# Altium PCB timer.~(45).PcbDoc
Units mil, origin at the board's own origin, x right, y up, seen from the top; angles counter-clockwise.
Board outline 1968.5 x 1968.5 mil, 2 copper layers (Top Layer, Bottom Layer); 56 components, 43 nets, 162 pads, 38 vias.
Unrouted connection lines stored in the file: 7.
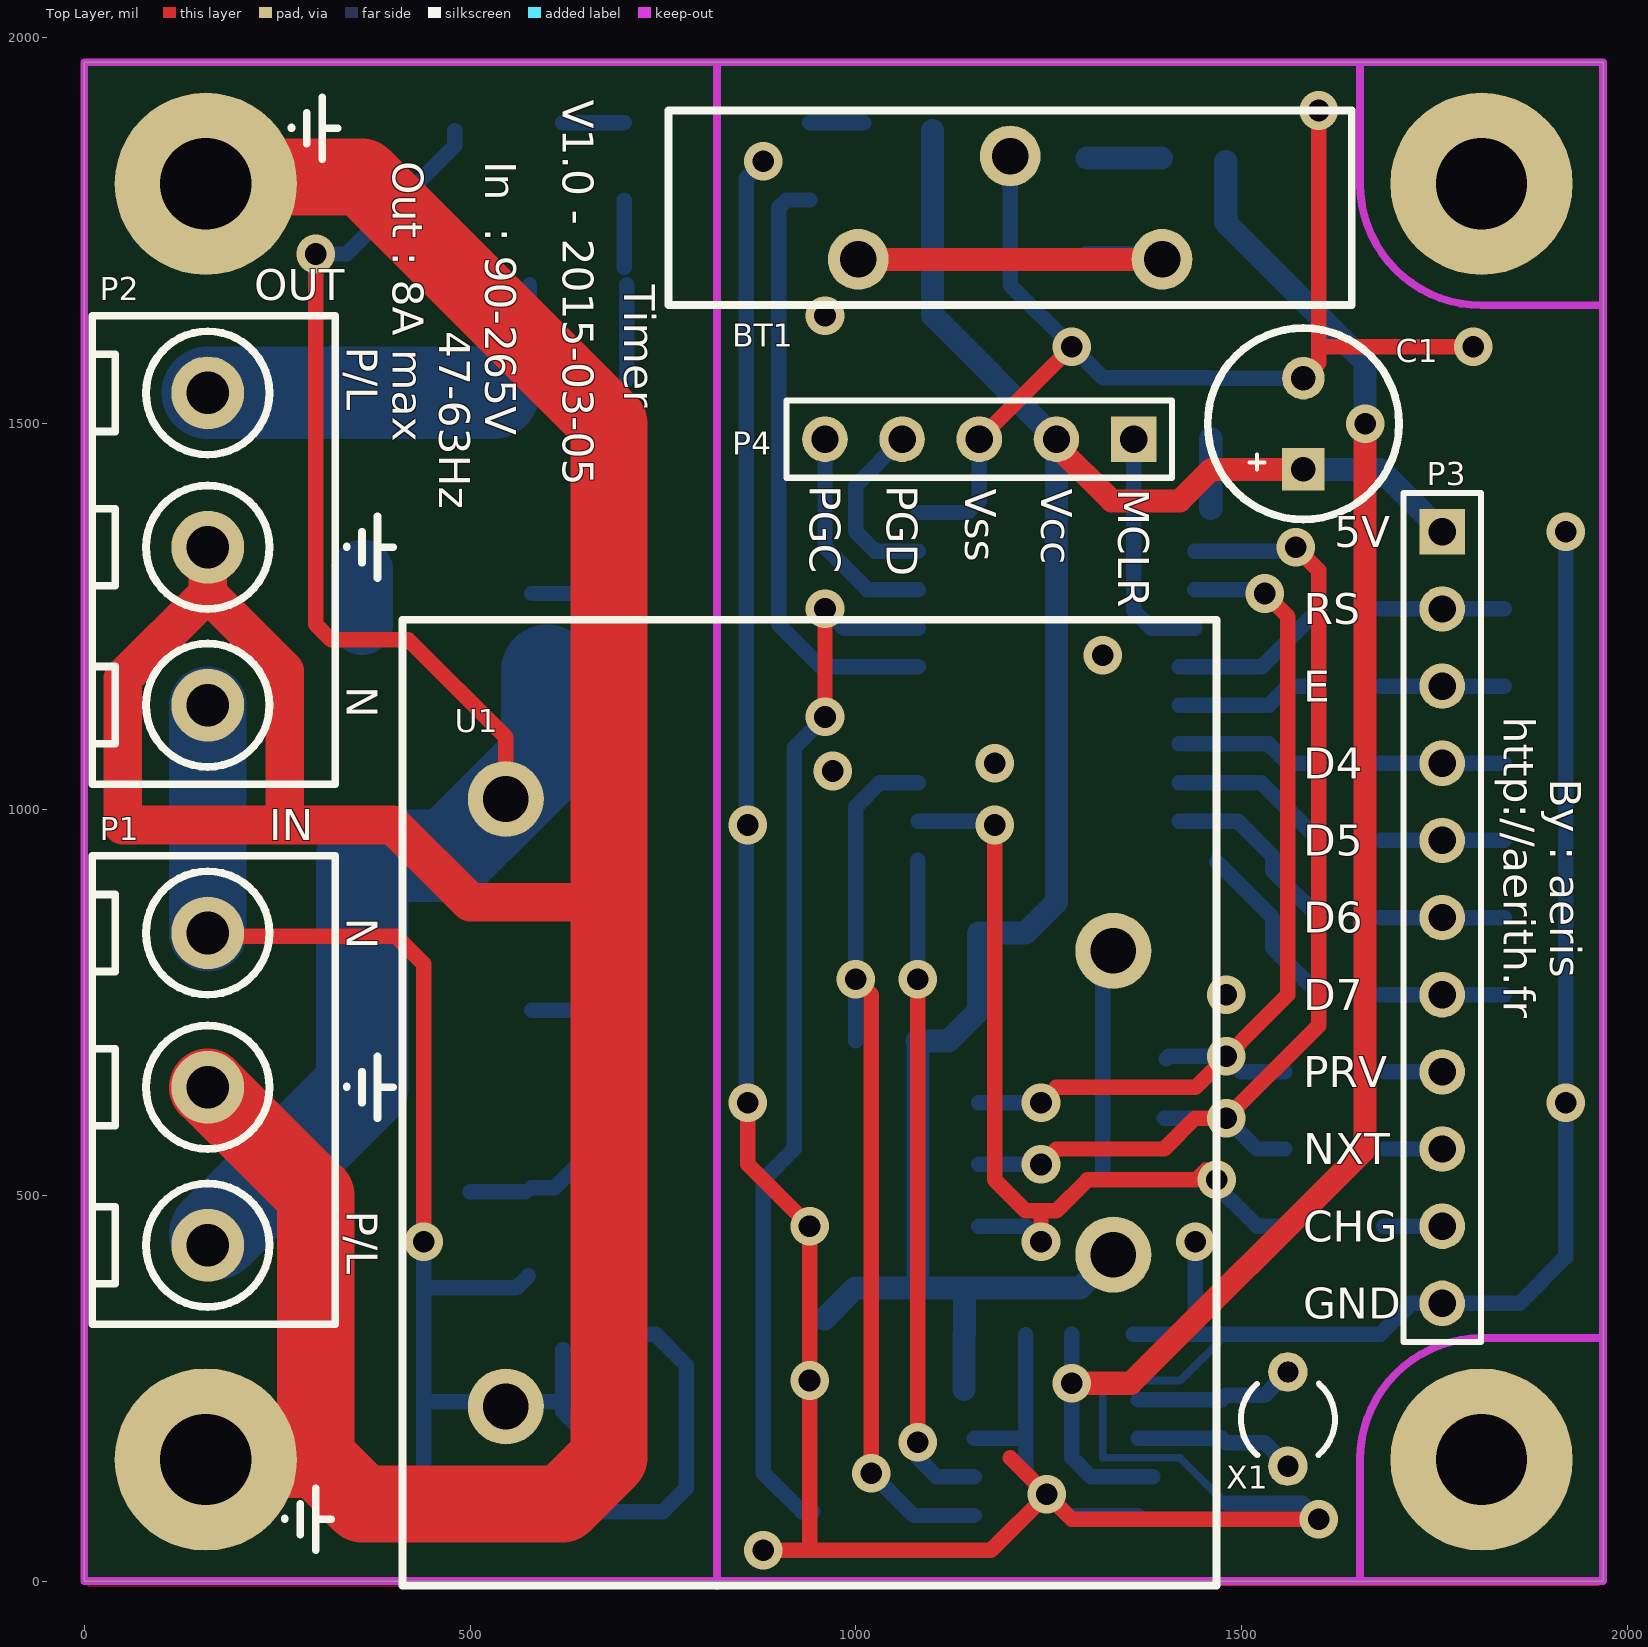
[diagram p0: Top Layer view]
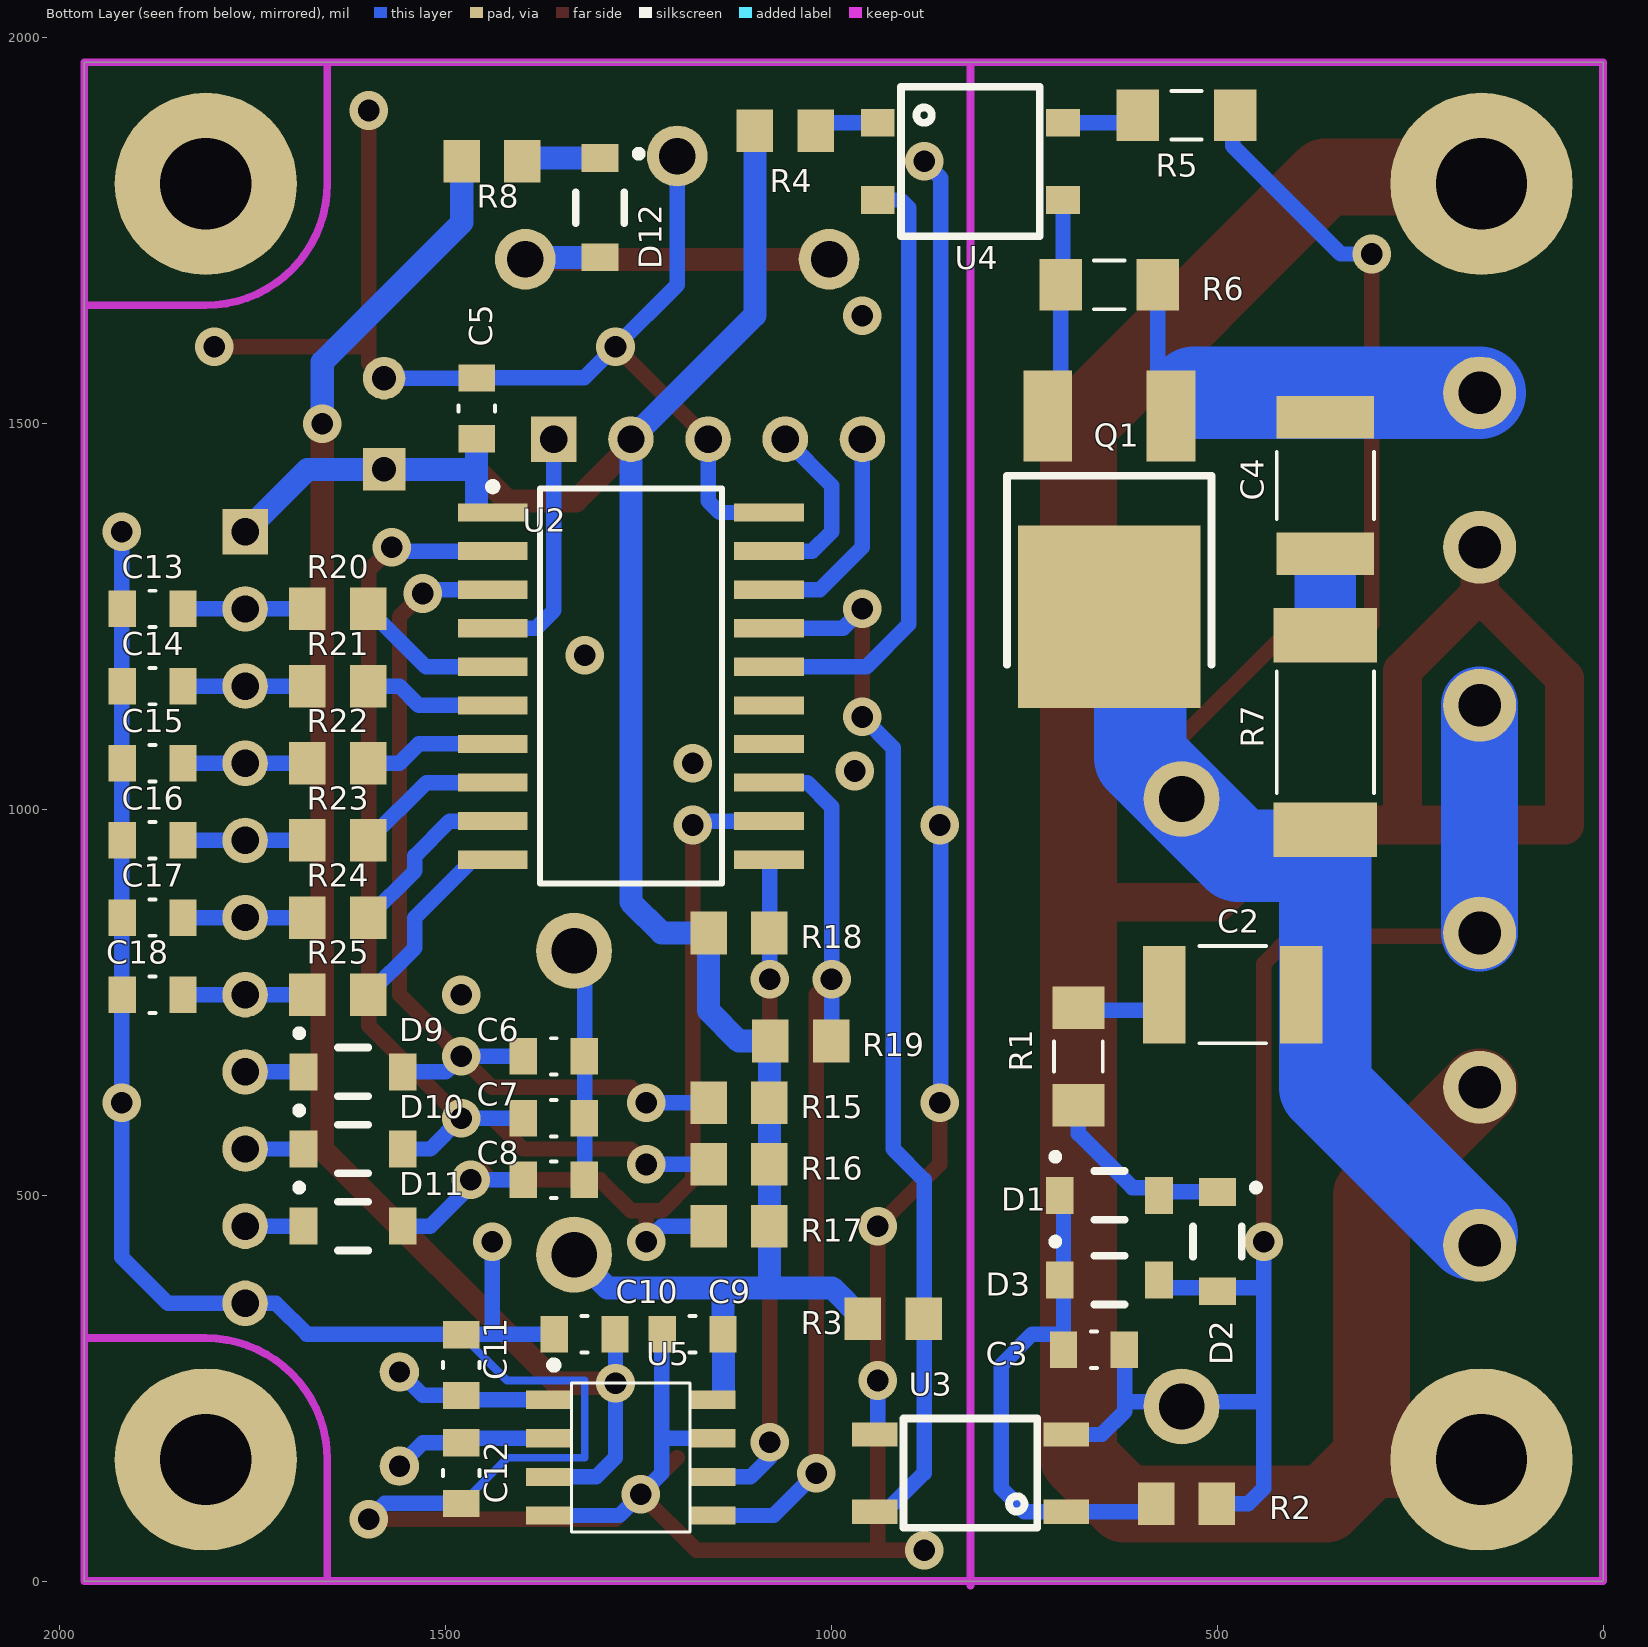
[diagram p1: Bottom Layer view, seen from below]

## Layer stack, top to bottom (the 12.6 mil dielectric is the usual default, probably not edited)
Top Layer: signal copper 1.4
Dielectric: core 12.6, FR-4, Dk 4.8
Bottom Layer: signal copper 1.4

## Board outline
0,0 1968.5,0 1968.5,1968.5 0,1968.5

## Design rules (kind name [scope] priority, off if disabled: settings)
Clearance RTC [InNetClass('RTC')] p1: gap=8
Clearance Earth [InNet('EARTH')] p2: gap=20
Clearance HT [InNetClass('HT') vs InNetClass('HT')] p3: gap=78.74
Clearance "plan masse" [All vs InNet('GND')] p4: gap=10
Clearance [All] p5: gap=20
HoleSize [All] p1: absolutevalues=TRUE maxlimit=196.85 minlimit=23.62 maxpercent=80.000 minpercent=20.000
PlaneConnect PlaneConnect_Via [isVia] p1: planeconnectstyle=Direct reliefexpansion=20 reliefentries=4 reliefconductorwidth=10 reliefairgap=10
PlaneConnect [All] p2: planeconnectstyle=Direct reliefexpansion=20 reliefentries=4 reliefconductorwidth=10 reliefairgap=10
PolygonConnect PolygonConnect_Via [IsVia] p1: connectstyle=Direct reliefconductorwidth=20 reliefentries=4 polygonreliefangle="90 Angle" airgapwidth=10
PolygonConnect [All] p2: connectstyle=Direct reliefconductorwidth=20 reliefentries=4 polygonreliefangle="90 Angle" airgapwidth=10
RoutingVias [All] p1: holewidth=39.37 width=78.74 viastyle="Through Hole" minholewidth=23.62 minwidth=31.5 maxholewidth=39.37 maxwidth=78.74
SilkToSolderMaskClearance SilkscreenOverComponentPads [IsPad] p1: minsilkscreentomaskgap=10 clearancetoexposedcopper=TRUE
SolderMaskExpansion [All] p1: expansion=4
Width overlay_width [(OnLayer('Top Overlay') OR OnLayer('Bottom Overlay'))] p1: maxlimit=10 minlimit=5 preferedwidth=10
Width [All] p2: maxlimit=150 minlimit=10 preferedwidth=20
25 further rules are at their usual default settings.

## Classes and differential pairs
net class RTC: NetC10_1 NetC11_1 NetC12_1
net class HT: N NetC4_1 NetC4_2 P

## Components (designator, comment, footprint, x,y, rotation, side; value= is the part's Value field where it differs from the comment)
BT1 "CR2032" BAT_2032 1200,1780 r0 top locked
C1 "470µ" CAP_6.3x2.5 1580,1500 r90 top locked
C2 "10n 400V" C1812 480,760 r0 bottom
C3 "10n" C0805 660,300 r180 bottom
C4 "10n 400V" C1812 360,1420 r90 bottom
C5 "100n" C0805 1460,1520 r270 bottom
C6 "100n" C0805 1360,680 r180 bottom
C7 "100n" C0805 1360,600 r180 bottom
C8 "100n" C0805 1360,520 r180 bottom
C9 "100n" C0805 1180,320 r0 bottom
C10 "100p" C0805 1320,320 r0 bottom
C11 "15p" C0805 1480,280 r90 bottom
C12 "15p" C0805 1480,140 r270 bottom
C13 "47p" C0805 1880,1260 r0 bottom
C14 "47p" C0805 1880,1160 r0 bottom
C15 "47p" C0805 1880,1060 r0 bottom
C16 "47p" C0805 1880,960 r0 bottom
C17 "47p" C0805 1880,860 r0 bottom
C18 "47p" C0805 1880,760 r0 bottom
D1 "MBR0520LT" SOD-123 640,500 r0 bottom
D2 "MBR0520LT" SOD-123 500,440 r90 bottom
D3 "5V1" SOD-123 640,390 r0 bottom
D9 "MBR0520LT" SOD-123 1620,660 r0 bottom
D10 "MBR0520LT" SOD-123 1620,560 r0 bottom
D11 "MBR0520LT" SOD-123 1620,460 r0 bottom
D12 "MBR0520LT" SOD-123 1300,1780 r90 bottom
P1 "5.08x3" "BORNIER 5.08X3" 160,640 r270 top locked
P2 "5.08x3" "BORNIER 5.08X3" 160,1340 r270 top locked
P3 "2.54x11" HDR1X11 1760,1360 r270 top locked
P4 "2.54x5" HDR1X5 1360,1480 r180 top locked
Q1 "BT137S-600D" DPAK 640,1310 r0 bottom
R1 "10k" R1206 680,680 r90 bottom
R2 "100k" R0805 540,100 r180 bottom
R3 "10k" R0805 920,340 r0 bottom
R4 "1k" R0805 1060,1880 r0 bottom
R5 "56" R1206 540,1900 r0 bottom
R6 "330" R1206 640,1680 r0 bottom
R7 "100 1W" R2512 360,1100 r90 bottom
R8 "1k" R0805 1440,1840 r0 bottom
R15 "10k" R0805 1120,620 r180 bottom
R16 "10k" R0805 1120,540 r180 bottom
R17 "10k" R0805 1120,460 r180 bottom
R18 "2k2" R0805 1120,840 r180 bottom
R19 "2k2" R0805 1040,700 r180 bottom
R20 "1k" R0805 1640,1260 r0 bottom
R21 "1k" R0805 1640,1160 r0 bottom
R22 "1k" R0805 1640,1060 r0 bottom
R23 "1k" R0805 1640,960 r0 bottom
R24 "1k" R0805 1640,860 r0 bottom
R25 "1k" R0805 1640,760 r0 bottom
U1 "AC-DC 5V 600mA" "AC-DC 3W" 940,620 r0 top locked
U2 "PIC16F1825" SOIC-20 1260,1160 r180 bottom locked
U3 "PC357N14J00F" OPTO_PC357N14J00F 820,140 r0 bottom
U4 "VOM160RT" OPTO_VOM160RT 820,1840 r180 bottom
U5 "MCP7940N" SOIC-8 1260,160 r180 bottom locked
X1 "32.768kHz" R38 1560,210 r0 top locked

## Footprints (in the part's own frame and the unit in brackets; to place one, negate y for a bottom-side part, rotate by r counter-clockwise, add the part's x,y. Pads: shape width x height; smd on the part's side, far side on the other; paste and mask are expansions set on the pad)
"AC-DC 3W" [mm]
  round 2.5 hole 1.5: 1(-10,10) 2(-10,-10) 3(10,-5) 4(10,5)
  silkscreen extent -13.4,-15.9 13.4,15.9, body extent -13.4,-15.9 13.4,15.9, height 19.5
BAT_2032 [mm] "Battery holder 2032"
  round 2 hole 1.2: +(-5,-1.7) +(5,-1.7) -(0,1.7)
  silkscreen extent -11.25,-3.2 11.25,3.2, body extent -11.25,-3.2 11.25,3.2, height 25
"BORNIER 5.08X3" [mm] "Bornier 5.08x3"
  round 2.4 hole 1.4: 1(-5.08,0) 2(0,0) 3(5.2,0)
  silkscreen extent -7.62,-3.8 7.8,4.2
C0805 [mm]
  rect 0.9x1.2 smd: 1(-1,0) 2(1,0)
  silkscreen extent -0.1,-0.6 0.1,0.6, body extent -1,-0.6 1,0.6, height 1.2
C1812 [mm]
  rect 1.4x3.2 smd: 1(-2.25,0) 2(2.25,0)
  silkscreen extent -1.1,-1.6 1.1,1.6, body extent -2.25,-1.6 2.25,1.6, height 3.2
CAP_6.3x2.5 [mm] "Capacitor throug hole dia=6.3mm, H=11mm, spacing=2.5mm"
  rect 1.4x1.4 hole 0.8: 1(-1.5,0)
  round 1.4 hole 0.8: 2(1.5,0)
  silkscreen extent -3.15,-3.15 3.15,3.15, body extent -3.12,-3.14 3.15,3.14, height 11
DPAK [mm] "DPAK"
  rect 1.6x3 smd: 1(-2.032,-5.08) 3(2.032,-5.08)
  rect 6x6 smd: 2(0,1.524)
  silkscreen extent -3.36,-3.11 3.36,3.11, body extent -3.36,-3.11 3.36,3.11, height 2.38
HDR1X5 [mm] "Connector; Header; 5 Position"
  rect 1.5x1.5 hole 0.9: 1(0,0)
  round 1.5 hole 0.9: 2(2.54,0) 3(5.08,0) 4(7.62,0) 5(10.16,0)
  silkscreen extent -1.27,-1.27 11.43,1.27
HDR1X11 [mm] "Connector; Header; 11 Position"
  rect 1.5x1.5 hole 0.9: 1(0,0)
  round 1.5 hole 0.9: 2(2.54,0) 3(5.08,0) 4(7.62,0) 5(10.16,0) 6(12.7,0) 7(15.24,0) 8(17.78,0) 9(20.32,0) 10(22.86,0) 11(25.4,0)
  silkscreen extent -1.27,-1.27 26.67,1.27
OPTO_PC357N14J00F [mm] "optocoupleur"
  rect 1.5x0.8 smd: 1(-3.15,1.27) 2(-3.15,-1.27) 3(3.15,-1.27) 4(3.15,1.27)
  silkscreen extent -2.2,-1.8 2.2,1.8, body extent -2.2,-1.8 2.2,1.8, height 2.6
OPTO_VOM160RT [mm] "Opto-triac"
  rect 1.11x0.91 smd: 1(-3.048,1.27) 2(-3.048,-1.27) 3(3.048,-1.27) 4(3.048,1.27)
  silkscreen extent -2.28,-2.46 2.28,2.46, body extent -2.28,-2.46 2.28,2.46, height 1.97
R38 [mm] "Crystal, Thru-Hole; 2 Leads; Body 3.1 x 8.2 mm (Dia.xH)"
  round 1.3 hole 0.7: 1(0,1.55) 2(0,-1.55)
  silkscreen extent -1.55,-1.19 1.55,1.17
R0805 [mm] "0.125W"
  rect 1.2x1.4 smd: 1(-1,0) 2(1,0)
  body extent -1,-0.63 1,0.63, height 1.2
R1206 [mm] "0.25W"
  rect 1.4x1.7 smd: 1(-1.6,0) 2(1.6,0)
  silkscreen extent -0.5,-0.8 0.5,0.8, body extent -1.6,-0.8 1.6,0.8, height 1.6
R2512 [mm] "1W"
  rect 1.8x3.4 smd: 1(-3.2,0) 2(3.2,0)
  silkscreen extent -2,-1.6 2,1.6, body extent -3.2,-1.6 3.2,1.6, height 5
SOD-123 [mm] "Diode"
  rect 0.91x1.22 smd: 1(-1.635,0) 2(1.635,0)
  silkscreen extent -0.5,-1.37 1.88,0.8, body extent -1.35,-0.8 1.35,0.8, height 1.17
SOIC-8 [mm] "8-Pin Plastic Narrow Body Small Outline Integrated Circuit 1.27 mm Pitch, IPC Medium Density"
  rect 1.5x0.6 smd: 1(-2.7,1.905) 2(-2.7,0.635) 3(-2.7,-0.635) 4(-2.7,-1.905) 5(2.7,-1.905) 6(2.7,-0.635) 7(2.7,0.635) 8(2.7,1.905)
  silkscreen extent -2.67,-2.45 1.95,3.17, body extent -1.95,-2.45 1.95,2.45, height 1.76
SOIC-20 [mm] "20-Pin Plastic Wide Body Small Outline Integrated Circuit 1.27 mm Pitch, IPC Medium Density"
  rect 2.3x0.6 smd: 1(-4.55,5.715) 2(-4.55,4.445) 3(-4.55,3.175) 4(-4.55,1.905) 5(-4.55,0.635) 6(-4.55,-0.635) 7(-4.55,-1.905) 8(-4.55,-3.175) 9(-4.55,-4.445) 10(-4.55,-5.715) 11(4.55,-5.715) 12(4.55,-4.445) 13(4.55,-3.175) 14(4.55,-1.905) 15(4.55,-0.635) 16(4.55,0.635) 17(4.55,1.905) 18(4.55,3.175) 19(4.55,4.445) 20(4.55,5.715)
  silkscreen extent -4.67,-6.5 3,6.69, body extent -3.75,-6.4 3.75,6.4, height 2.65

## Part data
BT1: library part Battery, "Multicell Battery"
C1: library part "Cap Pol1", "Polarized Capacitor (Radial)"
C2 C3 C4 C5 C6 C7 C8 C9 C10 C11 C12 C13 C14 C15 C16 C17 C18: library part Cap, "Capacitor"
D1 D2 D9 D10 D11 D12: library part "Diode 1N4001", "1 Amp General Purpose Rectifier"
D3: library part "D Zener", "Zener Diode"
P1 P2: library part "Header 3", "Header, 3-Pin"
P3: library part "Header 11", "Header, 11-Pin"
P4: library part "Header 5", "Header, 5-Pin"
Q1: library part Triac, "Silicon Bidirectional Triode Thyristor"
R1 R2 R3 R4 R5 R6 R7 R8 R15 R16 R17 R18 R19 R20 R21 R22 R23 R24 R25: library part Res2, "Resistor"
U1: library part AC-DC
U2: library part PIC16F1829
U3: library part Optoisolator1, "4-Pin Phototransistor Optocoupler"
U4: library part "Opto TRIAC", "Opto-Triac"
U5: library part "RTC- MCP7940N"
X1: library part XTAL, "Crystal Oscillator"

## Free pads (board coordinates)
  round 236.22 hole 118.11: 0(157.48,157.48) 0(157.48,1811.02) 0(1811.02,157.48) 0(1811.02,1811.02)

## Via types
v1: diameter 50, hole 28, Top Layer to Bottom Layer, 38 vias

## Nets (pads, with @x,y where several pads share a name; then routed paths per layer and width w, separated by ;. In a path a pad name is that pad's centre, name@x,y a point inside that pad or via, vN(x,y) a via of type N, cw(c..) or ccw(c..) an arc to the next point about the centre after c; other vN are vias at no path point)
BP_CHG: C8.1 D11.1 R17.1 U2.12 | length 1201.3
  Top Layer w20: v1(1180,980) 1180,520 1220,480 1240,480 ; v1(1240,440) 1240,480 ; v1@1454.33,515.43 1454.33,533.23 1441.1,520 1300,520 1260,480 1240,480
  Bottom Layer w20: U2.12 1175,985 v1(1180,980) ; R17.1 1220,460 v1(1240,440) ; C8.1@1400,520 1460,520 1520,460 D11.1
  other v1: 1467.56,520
BP_NXT: C7.1 D10.1 R16.1 U2.2 | length 1453.4
  Top Layer w20: v1(1240,540) 1260,560 1399.69,560 1439.69,600 v1(1480,600) 1600,720 1600,1310 v1(1570,1340)
  Bottom Layer w20: R16.1 v1(1240,540) ; C7.1 v1(1480,600) 1520,560 D10.1 ; U2.2 1565,1335 v1(1570,1340)
BP_PRV: C6.1 D9.1 R15.1 U2.3 | length 1246.8
  Top Layer w20: v1(1240,620) 1260,640 1440,640 1560,760 1560,1250 v1(1530,1280)
  Bottom Layer w20: R15.1 v1(1240,620) ; C6.1@1402.38,676.99 1405.39,680 v1(1480,680) 1500,660 D9.1 ; U2.3 1525,1285 v1(1530,1280)
EARTH: P1.2 P2.2 pad.0@157.48,157.48 pad.0@157.48,1811.02 | length 4671.4
  Top Layer w50: P2.2 160,1280 ; 680,880 500,880 400,980 260,980 ; 160,1280 50,1170 50,980 260,980 ; 160,1280 260,1180 260,980
  Top Layer w100: pad.0@157.48,1811.02 166.46,1820 360,1820 680,1500 680,880 680,160 620,100 360,100 302.52,157.48 157.48,157.48 300,157.48 300,500 P1.2
GND: BT1.- C1.2 C5.1 C6.2 C7.2 C8.2 C9.2 C10.2 C11.2 C12.2 C13.2 C14.2 C15.2 C16.2 C17.2 C18.2 P3.11 P4.3 U1.4 U2.20 U3.3 U5.4 U5.7 | length 7217.7
  Top Layer w20: v1(860,620) 860,540 v1(940,460) v1(940,260) 940,40 ; v1(880,40) 940,40 ; P4.3 v1(1280,1600) ; 1200,160 v1(1247.5,112.5) ; C1.2 1600,1579.06 1600,1600 ; v1(1600,80) 1280,80 v1(1247.5,112.5) ; v1(1600,1905.98) 1600,1600 ; v1(1800,1600) 1600,1600 ; 940,40 1175,40 v1(1247.5,112.5)
  Bottom Layer w10: C12.2@1479.37,100.63 1420,160 1320,160 1320,260 1420.63,260 C11.2
  Bottom Layer w20: v1@858.19,620 858.19,1818.19 v1(880,1840) ; U3.3@940,194.02 v1(940,260) ; U2.20 1145,1385 1160,1400 P4.3 ; U5.7 1220,185 ; BT1.- 1200,1680 v1(1280,1600) 1320.63,1559.37 C5.1 ; C9.2@1220,319.37 1220,185 ; C8.2@1320,520.63 U1.4@1320,840 ; C10.2 C11.2@1479.37,320 ; U5.4 1275,85 v1(1247.5,112.5) 1220,140 1220,185 ; 1440,320 v1(1440,440) ; C5.1@1460.32,1559.06 C1.2 ; C12.2 1579.37,100.63 v1(1600,80) ; C11.2@1480.63,320 1680,320 1720,360 1860,360 1920,420 v1(1920,1360)
  other v1: 1920,620 1480,760 860,980 970,1050 1180,1060 1320,1200 960,1640
LCD_D4: R22.1 U2.7 | length 191.9
  Bottom Layer w20: U2.7@1419.13,1085 1535,1085 1560,1060 R22.1
LCD_D5: R23.1 U2.8 | length 212.6
  Bottom Layer w20: U2.8@1419.13,1035 1525,1035 1560,1000 1560.63,1000 R23.1
LCD_D6: R24.1 U2.9 | length 244.6
  Bottom Layer w20: U2.9@1419.13,985 1495,985 1540,940 1540,920.63 R24.1
LCD_D7: R25.1 U2.10 | length 227.6
  Bottom Layer w20: U2.10@1467.56,932.44 1540,860 1540,820.63 R25.1
LCD_E: R21.1 U2.6 | length 191.9
  Bottom Layer w20: U2.6@1419.13,1135 1535,1135 1560,1160 R21.1
LCD_RS: R20.1 U2.5 | length 212.6
  Bottom Layer w20: U2.5@1419.13,1185 1525.63,1185 R20.1
MCLR: P4.1 U2.4 | length 310.6
  Bottom Layer w20: P4.1 1360,1258.11 1383.11,1235 U2.4
N: C3.2 D2.1 D3.1 P1.1 P2.3 R2.2 U1.2 U3.2 | length 1834.8
  Top Layer w20: P1.1@164.25,835.75 404.25,835.75 440,800 v1(440,440)
  Bottom Layer w20: 440,380 560,380 D3.1@575.63,395.63 ; v1(440,440) 440,232.6 ; R2.2 460,100 440,120 440,232.6 ; 620,232.6 540,232.6 440,232.6 ; C3.2 620,300 620,220 650,190 U3.2
  Bottom Layer w50: U1.2@540,232.6 U1.2
  Bottom Layer w100: P1.1 P2.3
NetBT1_1: BT1.+ D12.1 | length 488
  Top Layer w30: BT1.+@1003.15,1713.07 BT1.+@1396.85,1713.07
  Bottom Layer w30: D12.1 BT1.+@1394.29,1715.63
NetC2_2: C2.2 R1.2 | length 100
  Bottom Layer w20: C2.2@580,740 R1.2@680,740
NetC3_1: C3.1 D1.2 D3.2 R2.1 U3.1 | length 639.6
  Bottom Layer w20: R2.1@580,90 U3.1 750,90 780,120 780,280 740,320 699.37,320 D1.2@699.37,490
NetC4_1: C4.1 R7.2 | length 70
  Bottom Layer w80: R7.2@360,1240 C4.1@360,1310
NetC4_2: C4.2 P2.1 Q1.1 R6.1 | length 523
  Bottom Layer w20: Q1.1@577.01,1527.01 R6.1
  Bottom Layer w120: P2.1 Q1.1@530,1540
NetC10_1: C10.1 R8.2 U5.3 | length 2135.9
  Top Layer w30: v1(1280,256.46) 1356.46,256.46 1660,560 v1(1660,1500)
  Bottom Layer w20: C10.1@1280,320 1280,160 1305,135 U5.3 U5.3@1385,135
  Bottom Layer w30: R8.2 1479.37,1760.63 1660,1580 v1(1660,1500)
NetC11_1: C11.1 U5.1 X1.1 | length 200.7
  Bottom Layer w20: U5.1 C11.1@1474.37,235 ; C11.1 1529.61,240.63 X1.1
NetC12_1: C12.1 U5.2 X1.2 | length 200.7
  Bottom Layer w20: U5.2 C12.1@1474.37,185 ; C12.1 1529.61,179.37 X1.2
NetD1_1: D1.1 D2.2 R1.1 | length 220.3
  Bottom Layer w20: D2.2 D1.1@571.26,504.37 ; D1.1@580,510 610,510 680,580 R1.1@680,600
NetD12_2: D12.2 R8.1 | length 96.3
  Bottom Layer w30: D12.2 R8.1@1396.26,1844.37
NetQ1_3: Q1.3 R6.2 U4.3 | length 210
  Bottom Layer w20: R6.2@700,1702.99 U4.3 ; Q1.3@702.99,1557.01 R6.2
NetR4_1: R4.1 U4.1 | length 70
  Bottom Layer w20: U4.1 R4.1@1010,1890
NetR5_2: R5.2 U4.4 | length 80
  Bottom Layer w20: R5.2@620,1890 U4.4
P: C2.1 P1.3 Q1.2 R5.1 R7.1 U1.1 | length 2179
  Top Layer w20: v1(300,1720) 300,1240 320,1220 420,1220 546.3,1093.7 U1.1
  Bottom Layer w20: v1(300,1720) 340,1720 480,1860 R5.1@480,1880 ; Q1.2@580,1280 Q1.2@660,1280
  Bottom Layer w120: P1.3@170,450 360,640 360,940 472.6,940 U1.1 600,1067.4 Q1.2@600,1180
P_BP_CHG: D11.2 P3.10 | length 75.6
  Bottom Layer w20: D11.2 P3.10
P_BP_NXT: D10.2 P3.9 | length 75.6
  Bottom Layer w20: D10.2 P3.9
P_BP_PRV: D9.2 P3.8 | length 75.6
  Bottom Layer w20: D9.2 P3.8
P_LCD_D4: C15.1 P3.4 R22.2 | length 161.3
  Bottom Layer w20: R22.2 P3.4 C15.1
P_LCD_D5: C16.1 P3.5 R23.2 | length 161.3
  Bottom Layer w20: R23.2 P3.5 C16.1
P_LCD_D6: C17.1 P3.6 R24.2 | length 161.3
  Bottom Layer w20: R24.2 P3.6 C17.1
P_LCD_D7: C18.1 P3.7 R25.2 | length 161.3
  Bottom Layer w20: R25.2 P3.7 C18.1
P_LCD_E: C14.1 P3.3 R21.2 | length 161.3
  Bottom Layer w20: R21.2 P3.3 C14.1
P_LCD_RS: C13.1 P3.2 R20.2 | length 161.3
  Bottom Layer w20: R20.2 P3.2 C13.1
PGC: P4.5 U2.18 | length 283.6
  Bottom Layer w20: P4.5 960,1340 1015,1285 U2.18
PGD: P4.4 U2.19 | length 236.1
  Bottom Layer w20: P4.4 1000,1420 1000,1360 1025,1335 U2.19
POWER: U2.16 U4.2 | length 787.8
  Bottom Layer w20: U4.2 910,1790 900,1780 900,1240 955,1185 U2.16
SCL: R18.2 U2.11 U5.6 | length 858.2
  Top Layer w20: v1(1080,180) v1(1080,780)
  Bottom Layer w20: v1(1080,180) 1080,160 1105,135 U5.6 ; v1(1080,780) U2.11@1080,934.13
SDA: R19.2 U2.13 U5.5 | length 1202.3
  Top Layer w20: v1(1000,780) 1020,760 v1(1020,140)
  Bottom Layer w20: R19.2@1000,700 1000,1003.65 1031.35,1035 U2.13 ; v1(1020,140) 1075,85 U5.5
SIGNAL: R3.1 U2.17 U3.4 | length 1369.1
  Top Layer w20: v1(960,1120) v1(960,1260)
  Bottom Layer w20: U3.4 930,90 880,140 880,520 920,560 920,1080 v1(960,1120) ; v1(960,1260) 985,1235 U2.17
VCC: C1.1 C5.2 C9.1 P3.1 P4.2 R3.2 R4.2 R15.2 R16.2 R17.2 R18.1 R19.1 U1.3 U2.1 U5.8 | length 3120.9
  Top Layer w30: P4.2 1260,1471.45 1331.45,1400 1420,1400 1460.94,1440.94 C1.1
  Bottom Layer w30: R3.2 999.37,380 1140.63,380 ; R19.1 1120,700 1159.37,739.37 R18.1 1220,840 1260,880 P4.2 1099.37,1640.63 R4.2 ; 1080.63,380 R16.2 ; R17.2 R16.2 ; R19.1@1080.63,700 R16.2 ; 1140,248.7 1140,320 C9.1 1140.63,380 ; U1.3 1290.55,380 1140.63,380 ; U2.1@1460,1390 1460,1440.32 ; C5.2 1460,1440.32 ; P3.1 1679.06,1440.94 C1.1 1460.63,1440.94 1460,1440.32
pads on no net: U2.14 U2.15

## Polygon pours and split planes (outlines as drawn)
GND on Bottom Layer "GND-Bottom" (solid, remove dead copper, shelved, pour order 5): 1968.5,0 820,0 820,1968.5 1968.5,1968.5
EARTH on Top Layer "Earth-Top" (solid, shelved, pour order 3): 0,0 5.98,-5.98 820,-5.98 820,1968.5 0,1968.5
GND on Top Layer "GND-Top" (solid, remove dead copper, shelved, pour order 7): 1968.5,0 1962.52,-5.98 820,-5.98 820,1968.5 1968.5,1968.5

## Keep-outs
Top Layer:
  lines w10: 820,-5.98 820,1968.5 ; 1653.54,0 1653.54,157.48 cw(c1811.02,157.48) 1811.02,314.96 1968.5,314.96 ; 1653.54,1968.5 1653.54,1811.02 ccw(c1811.02,1811.02) 1811.02,1653.54 1968.5,1653.54
Bottom Layer:
  lines w10: 820,-5.98 820,1968.5 ; 1653.54,0 1653.54,157.48 cw(c1811.02,157.48) 1811.02,314.96 1968.5,314.96 ; 1653.54,1968.5 1653.54,1811.02 ccw(c1811.02,1811.02) 1811.02,1653.54 1968.5,1653.54
Keep-Out Layer:
  the board outline again, w10

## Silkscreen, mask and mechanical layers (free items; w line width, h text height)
Top Overlay:
  lines w10: 260,80 260,81 ; 268.5,1882.99 268.5,1883.99 ; 280,60 280,100 ; 288.5,1862.99 288.5,1902.99 ; 300,40 300,120 ; 300,80 320,80 ; 308.5,1842.99 308.5,1922.99 ; 308.5,1882.99 328.5,1882.99 ; 340,640 340,641 ; 340,1340 340,1341 ; 360,620 360,660 ; 360,1320 360,1360 ; 380,600 380,680 ; 380,640 400,640 ; 380,1300 380,1380 ; 380,1340 400,1340
  text "V1.0 - 2015-03-05" at 620,1920 h40 r270
  text "Out : 8A max" at 400,1840 h40 r270
  text "In  : 90-265V" at 520,1840 h40 r270
  text "Timer" at 700,1680 h40 r270
  text "OUT" at 220,1660 h40
  text "47-63Hz" at 460,1620 h40 r270
  text "P/L" at 340,1600 h40 r270
  text "PGC" at 940,1420 h40 r270
  text "PGD" at 1040,1420 h40 r270
  text "Vss" at 1141.89,1415.91 h40 r270
  text "Vcc" at 1240,1415.91 h40 r270
  text "MCLR" at 1340,1415.91 h40 r270
  text "5V" at 1620,1340 h40
  text "RS" at 1580.63,1240 h40
  text "N" at 340,1160 h40 r270
  text "E" at 1580,1140 h40
  text "http://aerith.fr" at 1840,1120 h40 r270
  text "D4" at 1580,1040 h40
  text "By : aeris" at 1900,1040 h40 r270
  text "IN" at 240,960 h40
  text "D5" at 1580,940 h40
  text "N" at 340,860 h40 r270
  text "D6" at 1580,840 h40
  text "D7" at 1580,740 h40
  text "PRV" at 1580,640 h40
  text "NXT" at 1580,540 h40
  text "P/L" at 340,480 h40 r270
  text "CHG" at 1580,440 h40
  text "GND" at 1580,340 h40

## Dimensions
0,0 to 0,1968.5 on Drill Guide
1968.5,1968.5 to 0,1968.5 on Drill Guide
